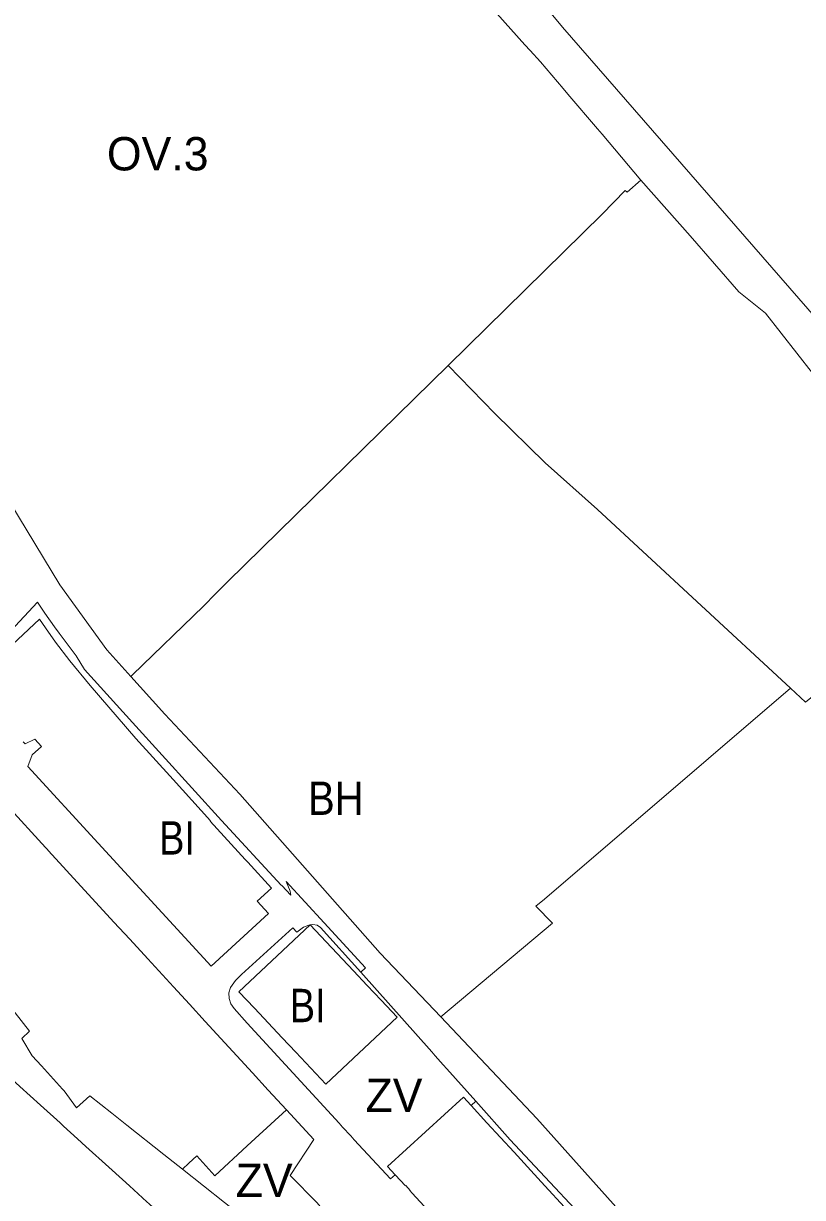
# Model space of a CAD drawing. Extents: x -650451 to -642268, y -1075216 to -1066610.
# Drawn here: x -646344.3 to -646064, y -1072120.7 to -1071698.5 of the extents above; entities that cross this region are included whole.
import ezdxf

# ---------------------------------------------------------------- set-up
doc = ezdxf.new("R2010")
doc.units = 0
doc.header["$LTSCALE"] = 4.8
for name, color, linetype, lineweight in [('1', 7, 'Continuous', 13), ('11', 7, 'Continuous', 13), ('15', 7, 'Continuous', 13), ('2', 7, 'Continuous', 13), ('24', 7, 'Continuous', 13), ('40', 7, 'Continuous', 13), ('43', 7, 'Continuous', 13), ('46', 7, 'Continuous', 13), ('6', 7, 'Continuous', 13)]:
    doc.layers.add(name, color=color, linetype=linetype, lineweight=lineweight)
doc.layers.add('62', color=7, linetype='Continuous')

msp = doc.modelspace()

# ---------------------------------------------------------------- linework, layer by layer
at = {"layer": '1'}
for points in [[(-646305.73, -1071933.35), (-646305.1, -1071932.73), (-646279.61, -1071908.02), (-646275.13, -1071903.51), (-646270.83, -1071899.21), (-646191.57, -1071821.44)], [(-646191.57, -1071821.44), (-646174.69, -1071838.69), (-646156.59, -1071856.53), (-646137.74, -1071873.31), (-646102.04, -1071906.4), (-646068.317, -1071937.555)], [(-646215.94, -1072032.8), (-646266.5, -1071975.69), (-646293.49, -1071946.89), (-646302.38, -1071937.06), (-646305.73, -1071933.35)], [(-646068.317, -1071937.555), (-646156.858, -1072013.393), (-646160, -1072016), (-646154, -1072022), (-646194.191, -1072055.797), (-646215.94, -1072032.8)]]:
    msp.add_lwpolyline(points, dxfattribs=at)
at = {"layer": '11'}
for points in [[(-646305.73, -1071933.35), (-646314.39, -1071923.77), (-646331.27, -1071900.42), (-646355.29, -1071860.97), (-646378.11, -1071821.99), (-646382.96, -1071812.65), (-646387.39, -1071804.2), (-646391.38, -1071796.27), (-646395.23, -1071787.02), (-646401.48, -1071766.63), (-646406.33, -1071750.8), (-646409.27, -1071742.67), (-646414.59, -1071728.79), (-646418.89, -1071716.1), (-646422.74, -1071708.61), (-646435.53, -1071681.73)], [(-646174.08, -1071694.82), (-646163.9, -1071706.08), (-646162.04, -1071708.13), (-646158.35, -1071712.22), (-646150.15, -1071721.86), (-646148.49, -1071723.82), (-646137.84, -1071736.34), (-646136.17, -1071738.31), (-646122.16, -1071754.78)], [(-646122.16, -1071754.78), (-646127.12, -1071759.15), (-646127.84, -1071758.53), (-646136.12, -1071767.07), (-646191.57, -1071821.44)], [(-646191.57, -1071821.44), (-646270.83, -1071899.21), (-646275.13, -1071903.51), (-646279.61, -1071908.02), (-646305.1, -1071932.73), (-646305.73, -1071933.35)]]:
    msp.add_lwpolyline(points, dxfattribs=at)
at = {"layer": '15'}
msp.add_line((-646183.28, -1072087.62), (-646181.609, -1072086.079), dxfattribs=at)
for points in [[(-646357.09, -1071925.59), (-646339.33, -1071906.58), (-646336.6, -1071910.5), (-646333.15, -1071915.44), (-646331.55, -1071917.74), (-646325.42, -1071925.87), (-646322.33, -1071930.79), (-646305.17, -1071949.86), (-646273.14, -1071985.13), (-646251.59, -1072008.34), (-646251.4, -1072008.54), (-646248.19, -1072012.02), (-646248.33, -1072010.57), (-646249.88, -1072007.03), (-646236.1, -1072021.93), (-646221.31, -1072038.09), (-646222.96, -1072039.72)], [(-646344.46, -1071956.82), (-646343.78, -1071957.56), (-646340.27, -1071955.92), (-646337.9, -1071958.49), (-646341.21, -1071961.54), (-646342.81, -1071965.72), (-646317.43, -1071993.33), (-646290.37, -1072022.79), (-646276.84, -1072037.51), (-646256.22, -1072018.57), (-646260.28, -1072014.15), (-646255.13, -1072009.41), (-646263.65, -1072000.13), (-646264.6, -1071999.11), (-646277.19, -1071985.4), (-646277.03, -1071985.24), (-646290.42, -1071970.41), (-646303.87, -1071955.61), (-646320.31, -1071936.58), (-646327.65, -1071927.72), (-646332.76, -1071920.98), (-646336.41, -1071915.88), (-646338.62, -1071912.69), (-646371.82, -1071943.75)], [(-646249.71, -1072089.21), (-646256.24, -1072082.11), (-646261.92, -1072075.92), (-646267.6, -1072069.74), (-646273.28, -1072063.55), (-646278.97, -1072057.37), (-646284.65, -1072051.18), (-646290.33, -1072045), (-646299.57, -1072034.94), (-646306.1, -1072027.84), (-646311.78, -1072021.65), (-646328.83, -1072003.1), (-646335.36, -1071995.99), (-646335.87, -1071995.44), (-646336.37, -1071994.89), (-646350.24, -1071979.79), (-646364.11, -1071964.7), (-646377.98, -1071949.6), (-646376.25, -1071948.01), (-646380.09, -1071943.87), (-646357.09, -1071925.59)], [(-646241.21, -1072022.61), (-646241.66, -1072022.73), (-646243.54, -1072023.53), (-646246.04, -1072025.34), (-646247.48, -1072023.7), (-646265.9, -1072040.56), (-646268.09, -1072042.67), (-646269.83, -1072045.14), (-646270.43, -1072047.11), (-646270.37, -1072049.18), (-646269.73, -1072051.09), (-646268.56, -1072052.8), (-646263.88, -1072058.07), (-646230.77, -1072094.02), (-646229.5, -1072095.41), (-646226.6, -1072098.55), (-646225.32, -1072099.94), (-646212.32, -1072114.01), (-646210.58, -1072112.56)], [(-646222.96, -1072039.72), (-646237.49, -1072023.64), (-646238.72, -1072022.79), (-646240.24, -1072022.48), (-646241.21, -1072022.61)], [(-646234.9, -1072127.22), (-646238.72, -1072122.6), (-646248.39, -1072112.76), (-646239.86, -1072099.92), (-646249.71, -1072089.21)], [(-646148.33, -1072125.65), (-646158.07, -1072115.05), (-646162.94, -1072109.74), (-646167.82, -1072104.44), (-646177.56, -1072093.84), (-646183.28, -1072087.62)], [(-646181.609, -1072086.079), (-646169.22, -1072099.97), (-646131.65, -1072140.05)], [(-646210.58, -1072112.56), (-646206.86, -1072116.57), (-646206.72, -1072116.45), (-646205.24, -1072118.2), (-646205.31, -1072118.26), (-646204.46, -1072119.17), (-646194.35, -1072130.11)]]:
    msp.add_lwpolyline(points, dxfattribs=at)
at = {"layer": '2'}
for points in [[(-646371.82, -1071943.75), (-646338.62, -1071912.69), (-646336.41, -1071915.88), (-646332.76, -1071920.98), (-646327.65, -1071927.72), (-646320.31, -1071936.58), (-646303.87, -1071955.61), (-646290.42, -1071970.41), (-646277.03, -1071985.24), (-646277.19, -1071985.4), (-646264.6, -1071999.11), (-646263.65, -1072000.13), (-646255.13, -1072009.41), (-646260.28, -1072014.15), (-646256.22, -1072018.57), (-646276.84, -1072037.51), (-646290.37, -1072022.79), (-646317.43, -1071993.33), (-646342.81, -1071965.72), (-646341.21, -1071961.54), (-646337.9, -1071958.49), (-646340.27, -1071955.92), (-646343.78, -1071957.56), (-646344.46, -1071956.82)], [(-646357.09, -1071925.59), (-646380.09, -1071943.87), (-646376.25, -1071948.01), (-646377.98, -1071949.6), (-646364.11, -1071964.7), (-646350.24, -1071979.79), (-646336.37, -1071994.89), (-646335.87, -1071995.44), (-646335.36, -1071995.99), (-646328.83, -1072003.1), (-646311.78, -1072021.65), (-646306.1, -1072027.84), (-646299.57, -1072034.94), (-646290.33, -1072045), (-646284.65, -1072051.18), (-646278.97, -1072057.37), (-646273.28, -1072063.55), (-646267.6, -1072069.74), (-646261.92, -1072075.92), (-646256.24, -1072082.11), (-646249.71, -1072089.21)], [(-646341.21, -1072069.74), (-646344.94, -1072063.53), (-646342.13, -1072060.94), (-646347.32, -1072054.31), (-646351.45, -1072049.03)], [(-646320.51, -1072084.13), (-646325.21, -1072088.45), (-646329.72, -1072082.41), (-646330.33, -1072081.74), (-646337.87, -1072073.42), (-646341.21, -1072069.74)], [(-646307.16, -1072094.67), (-646312.51, -1072090.43), (-646320.51, -1072084.13)], [(-646210.58, -1072112.56), (-646213.3, -1072109.63), (-646185.99, -1072084.68), (-646183.28, -1072087.62)], [(-646249.71, -1072089.21), (-646260.96, -1072099.56), (-646263.84, -1072102.2), (-646275.48, -1072112.89), (-646282.01, -1072105.79), (-646284.89, -1072108.44), (-646287.16, -1072110.52), (-646293.83, -1072105.24), (-646307.16, -1072094.67)], [(-646183.28, -1072087.62), (-646177.56, -1072093.84), (-646167.82, -1072104.44), (-646162.94, -1072109.74), (-646158.07, -1072115.05), (-646148.33, -1072125.65)], [(-646194.35, -1072130.11), (-646204.46, -1072119.17), (-646205.31, -1072118.26), (-646205.24, -1072118.2), (-646206.72, -1072116.45), (-646206.86, -1072116.57), (-646210.58, -1072112.56)]]:
    msp.add_lwpolyline(points, dxfattribs=at)
msp.add_lwpolyline([(-646241.21, -1072022.61), (-646235.42, -1072028.76), (-646225.56, -1072039.24), (-646220.62, -1072044.48), (-646215.69, -1072049.73), (-646209.9, -1072055.89), (-646235.54, -1072080.01), (-646246.37, -1072068.5), (-646251.27, -1072063.3), (-646261.27, -1072052.66), (-646266.87, -1072046.71)], close=True, dxfattribs=at)
at = {"layer": '24'}
for points in [[(-646209.322, -1071634.004), (-646200.32, -1071642.53), (-646160.52, -1071687.59), (-646150.43, -1071699.82), (-646003.04, -1071868.9), (-645975.01, -1071901.96), (-645930.57, -1071954.35), (-645883.81, -1072002.11), (-645874.53, -1072011.68), (-645820.57, -1072067.31), (-645770.72, -1072118.71), (-645744.42, -1072145.83), (-645666.4, -1072225.05), (-645664.88, -1072226.59), (-645596.405, -1072296.114)], [(-646435.53, -1071681.73), (-646422.74, -1071708.61), (-646418.89, -1071716.1), (-646414.59, -1071728.79), (-646409.27, -1071742.67), (-646406.33, -1071750.8), (-646401.48, -1071766.63), (-646395.23, -1071787.02), (-646391.38, -1071796.27), (-646387.39, -1071804.2), (-646382.96, -1071812.65), (-646378.11, -1071821.99), (-646355.29, -1071860.97), (-646331.27, -1071900.42), (-646314.39, -1071923.77), (-646305.73, -1071933.35)], [(-646122.16, -1071754.78), (-646136.17, -1071738.31), (-646137.84, -1071736.34), (-646148.49, -1071723.82), (-646150.15, -1071721.86), (-646158.35, -1071712.22), (-646162.04, -1071708.13), (-646163.9, -1071706.08), (-646174.08, -1071694.82)], [(-646002.93, -1071893.984), (-646026.64, -1071867.44), (-646043.49, -1071845.87), (-646077.32, -1071802.59), (-646087, -1071795), (-646104.5, -1071774.86), (-646122.16, -1071754.78)], [(-646221.31, -1072038.09), (-646236.1, -1072021.93), (-646249.88, -1072007.03), (-646248.33, -1072010.57), (-646248.19, -1072012.02), (-646251.4, -1072008.54), (-646251.59, -1072008.34), (-646273.14, -1071985.13), (-646305.17, -1071949.86), (-646322.33, -1071930.79), (-646325.42, -1071925.87), (-646331.55, -1071917.74), (-646333.15, -1071915.44), (-646336.6, -1071910.5), (-646339.33, -1071906.58), (-646357.09, -1071925.59)], [(-646305.73, -1071933.35), (-646302.38, -1071937.06), (-646293.49, -1071946.89), (-646266.5, -1071975.69), (-646215.94, -1072032.8), (-646194.191, -1072055.797)], [(-646196.17, -1072069.75), (-646197.45, -1072068.32), (-646222.96, -1072039.72), (-646221.31, -1072038.09)], [(-646194.191, -1072055.797), (-646159.66, -1072092.31), (-646123.06, -1072133.18), (-646095.44, -1072162.47)], [(-646181.609, -1072086.079), (-646192, -1072074.43), (-646193.3, -1072072.98), (-646196.17, -1072069.75)], [(-646131.65, -1072140.05), (-646169.22, -1072099.97), (-646181.609, -1072086.079)]]:
    msp.add_lwpolyline(points, dxfattribs=at)
at = {"layer": '40'}
for points in [[(-646210.58, -1072112.56), (-646212.32, -1072114.01), (-646225.32, -1072099.94), (-646226.6, -1072098.55), (-646229.5, -1072095.41), (-646230.77, -1072094.02), (-646263.88, -1072058.07), (-646268.56, -1072052.8), (-646269.73, -1072051.09), (-646270.37, -1072049.18), (-646270.43, -1072047.11), (-646269.83, -1072045.14), (-646268.09, -1072042.67), (-646265.9, -1072040.56), (-646247.48, -1072023.7), (-646246.04, -1072025.34), (-646243.54, -1072023.53), (-646241.66, -1072022.73), (-646241.21, -1072022.61)], [(-646241.21, -1072022.61), (-646240.24, -1072022.48), (-646238.72, -1072022.79), (-646237.49, -1072023.64), (-646222.96, -1072039.72)], [(-646222.96, -1072039.72), (-646197.45, -1072068.32), (-646196.17, -1072069.75), (-646193.3, -1072072.98)], [(-646193.3, -1072072.98), (-646192, -1072074.43), (-646181.609, -1072086.079), (-646183.28, -1072087.62)], [(-646183.28, -1072087.62), (-646185.99, -1072084.68), (-646213.3, -1072109.63), (-646210.58, -1072112.56)], [(-646287.16, -1072110.52), (-646284.89, -1072108.44), (-646282.01, -1072105.79), (-646275.48, -1072112.89), (-646263.84, -1072102.2), (-646260.96, -1072099.56), (-646249.71, -1072089.21)], [(-646249.71, -1072089.21), (-646239.86, -1072099.92), (-646248.39, -1072112.76), (-646238.72, -1072122.6), (-646234.9, -1072127.22)], [(-646234.9, -1072127.22), (-646238.03, -1072130.1), (-646249.36, -1072140.5), (-646287.16, -1072110.52)]]:
    msp.add_lwpolyline(points, dxfattribs=at)
msp.add_lwpolyline([(-646241.21, -1072022.61), (-646266.87, -1072046.71), (-646261.27, -1072052.66), (-646251.27, -1072063.3), (-646246.37, -1072068.5), (-646235.54, -1072080.01), (-646209.9, -1072055.89), (-646215.69, -1072049.73), (-646220.62, -1072044.48), (-646225.56, -1072039.24), (-646235.42, -1072028.76)], close=True, dxfattribs=at)
at = {"layer": '43'}
for points in [[(-646351.45, -1072049.03), (-646347.32, -1072054.31), (-646342.13, -1072060.94), (-646344.94, -1072063.53), (-646341.21, -1072069.74), (-646337.87, -1072073.42), (-646330.33, -1072081.74)], [(-646338.2, -1072087.54), (-646345.68, -1072080.75), (-646350.2, -1072076.65)], [(-646330.33, -1072081.74), (-646329.72, -1072082.41), (-646325.21, -1072088.45), (-646320.51, -1072084.13)], [(-646320.51, -1072084.13), (-646312.51, -1072090.43), (-646307.16, -1072094.67), (-646293.83, -1072105.24), (-646287.16, -1072110.52), (-646249.36, -1072140.5)], [(-646306.22, -1072116.58), (-646312.43, -1072110.94), (-646313.68, -1072109.81), (-646321.85, -1072102.39), (-646324.94, -1072099.59), (-646329.95, -1072095.03), (-646331.17, -1072093.93), (-646338.2, -1072087.54)], [(-646267.64, -1072151.6), (-646276.92, -1072143.18), (-646284.31, -1072136.47), (-646286.09, -1072134.85), (-646291.65, -1072129.81), (-646299.17, -1072122.98), (-646299.95, -1072122.27), (-646306.22, -1072116.58)]]:
    msp.add_lwpolyline(points, dxfattribs=at)
at = {"layer": '46'}
for points in [[(-645596.405, -1072296.114), (-645664.88, -1072226.59), (-645666.4, -1072225.05), (-645744.42, -1072145.83), (-645770.72, -1072118.71), (-645820.57, -1072067.31), (-645874.53, -1072011.68), (-645883.81, -1072002.11), (-645930.57, -1071954.35), (-645975.01, -1071901.96), (-646003.04, -1071868.9), (-646150.43, -1071699.82), (-646160.52, -1071687.59), (-646200.32, -1071642.53), (-646209.322, -1071634.004)], [(-646068.317, -1071937.555), (-646062.91, -1071942.55), (-646002.93, -1071893.984)], [(-646194.191, -1072055.797), (-646154, -1072022), (-646160, -1072016), (-646156.858, -1072013.393), (-646068.317, -1071937.555)], [(-646123.06, -1072133.18), (-646159.66, -1072092.31), (-646194.191, -1072055.797)]]:
    msp.add_lwpolyline(points, dxfattribs=at)
at = {"layer": '6'}
for points in [[(-646350.2, -1072076.65), (-646345.68, -1072080.75), (-646338.2, -1072087.54), (-646331.17, -1072093.93), (-646329.95, -1072095.03), (-646324.94, -1072099.59), (-646321.85, -1072102.39)], [(-646321.85, -1072102.39), (-646313.68, -1072109.81), (-646312.43, -1072110.94), (-646306.22, -1072116.58), (-646299.95, -1072122.27), (-646299.17, -1072122.98), (-646291.65, -1072129.81)]]:
    msp.add_lwpolyline(points, dxfattribs=at)

# ---------------------------------------------------------------- texts
at = {"layer": '62'}
for s, p in [('OV.3', (-646314.315, -1071751.305)), ('ZV', (-646221.273, -1072089.939)), ('ZV', (-646267.995, -1072120.597))]:
    msp.add_text(s, height=12, dxfattribs=at).set_placement(p)
for s, width, p in [('BH', 0.9, (-646241.983, -1071983.122)), ('BI', 0.85, (-646295.522, -1071997.388)), ('BI', 0.85, (-646248.53, -1072057.675))]:
    msp.add_text(s, height=12, dxfattribs=dict(at, width=width)).set_placement(p)

doc.saveas('drawing.dxf')
